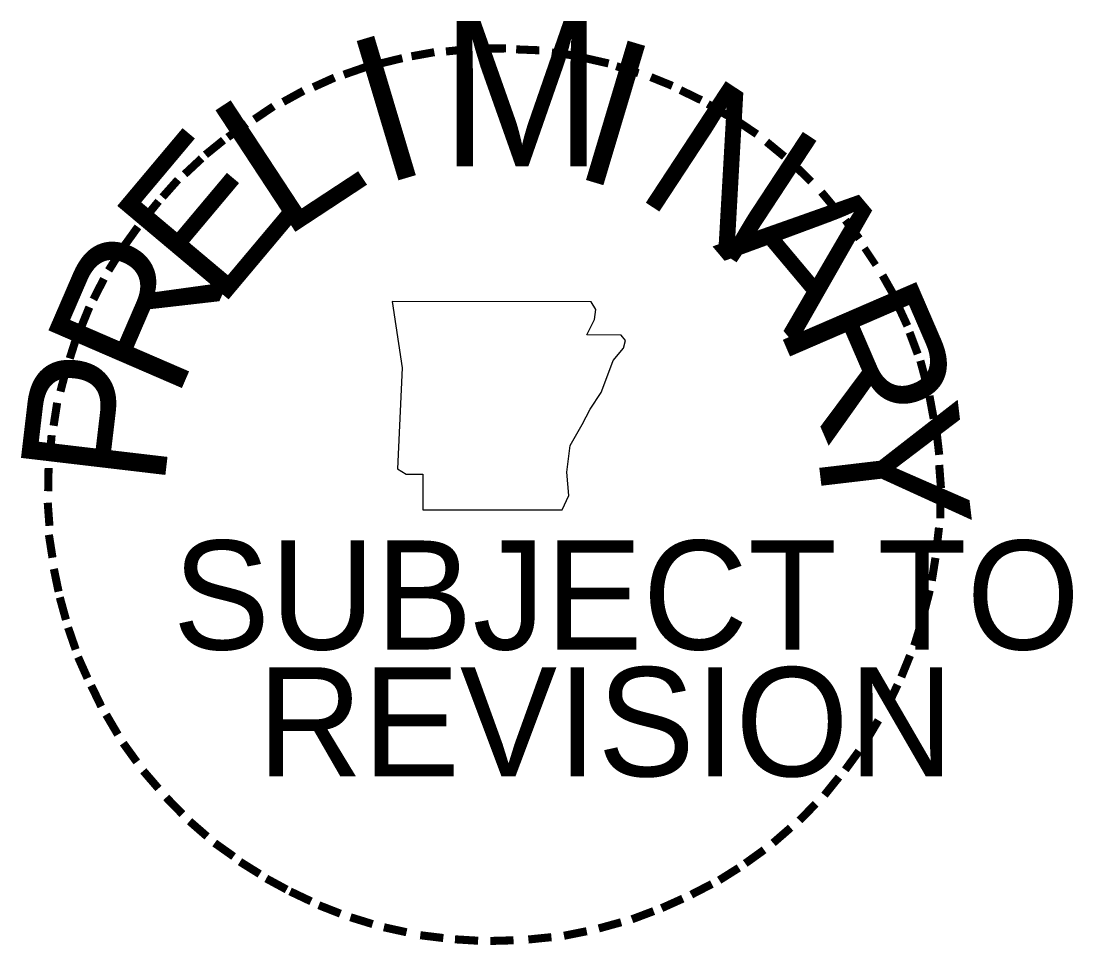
# Model space of a CAD drawing. Extents: x 541267 to 698737, y 790528 to 880942.
# Drawn here: x 687392 to 698737, y 793611 to 803574 of the extents above; entities that cross this region are included whole.
import ezdxf

# ---------------------------------------------------------------- set-up
doc = ezdxf.new("R2010")
doc.units = 0
doc.layers.add('R_Prelim_Stamp', color=7, linetype='Continuous')

msp = doc.modelspace()

# ---------------------------------------------------------------- linework, layer by layer
at = {"layer": 'R_Prelim_Stamp'}
msp.add_lwpolyline([(691394, 800549), (691501, 799833), (691452, 798747), (691547, 798687), (691726, 798687), (691726, 798305), (693229, 798304), (693301, 798459), (693277, 798709), (693313, 798996), (693445, 799223), (693529, 799389), (693648, 799568), (693720, 799759), (693780, 799914), (693888, 800046), (693912, 800129), (693864, 800188), (693494, 800189), (693577, 800356), (693590, 800464), (693540, 800546)], close=True, dxfattribs=at)

# ---------------------------------------------------------------- texts
for s, height, p in [('M', 1568, (691919, 802007)), ('SUBJECT TO', 1175.7, (689029, 796797)), ('REVISION', 1175.7, (689941, 795430))]:
    msp.add_text(s, height=height, dxfattribs=at).set_placement(p)
for s, height, rotation, p in [('I', 1568, 16.6559, (691277, 801801)), ('-', 766, 5.8968, (691960, 802947)), ('-', 766, 0.1862, (692329, 802982)), ('-', 766, 357.743, (692675, 802975)), ('I', 1568, 343.3441, (693300, 801916)), ('-', 766, 13.6302, (691287, 802817)), ('-', 766, 10.2193, (691611, 802895)), ('-', 766, 352.1617, (693031, 802949)), ('-', 766, 347.2049, (693375, 802894)), ('-', 766, 19.1761, (690928, 802702)), ('-', 766, 342.3362, (693679, 802820)), ('-', 766, 24.3072, (690625, 802573)), ('-', 766, 337.8551, (694031, 802713)), ('-', 766, 28.7918, (690322, 802421)), ('N', 1568, 326.6882, (693987, 801710)), ('-', 766, 334.1211, (694333, 802584)), ('L', 1568, 33.3118, (690207, 801207)), ('-', 766, 34.0636, (690036, 802244)), ('-', 766, 329.6409, (694610, 802448)), ('-', 766, 325.8627, (694917, 802275)), ('E', 1568, 49.9677, (689520, 800441)), ('-', 766, 36.2317, (689760, 802055)), ('-', 766, 38.9507, (689532, 801874)), ('-', 766, 320.5297, (695209, 802072)), ('-', 766, 42.9622, (689325, 801675)), ('-', 766, 315.5786, (695496, 801838)), ('-', 766, 48.4231, (689110, 801446)), ('-', 766, 309.8797, (695768, 801575)), ('-', 766, 50.6142, (688917, 801214)), ('A', 1568, 310.0323, (694847, 801147)), ('-', 766, 54.2325, (688720, 800942)), ('-', 766, 306.6522, (696019, 801287)), ('R', 1568, 66.6235, (689059, 799459)), ('-', 766, 58.0706, (688564, 800690)), ('-', 670, 303.6753, (696252, 801015)), ('-', 766, 62.8713, (688415, 800397)), ('-', 766, 299.6684, (696404, 800725)), ('R', 1568, 293.3765, (695540, 800295)), ('-', 766, 67.7743, (688291, 800104)), ('-', 766, 294.6628, (696559, 800432)), ('-', 766, 72.3945, (688186, 799803)), ('-', 766, 290.5728, (696682, 800156)), ('P', 1568, 83.2794, (688929, 798509)), ('-', 766, 285.1233, (696794, 799878)), ('-', 766, 75.461, (688092, 799461)), ('-', 766, 81.2013, (688029, 799120)), ('Y', 1568, 276.7206, (695931, 799353)), ('-', 766, 280.5493, (696890, 799523)), ('-', 766, 85.1863, (687992, 798789)), ('-', 766, 276.5962, (696967, 799156)), ('-', 766, 274.3301, (696996, 798810)), ('-', 766, 89.0622, (687980, 798454)), ('-', 766, 269.9407, (697012, 798508)), ('-', 766, 94.1959, (687997, 798107)), ('-', 766, 263.5172, (697003, 798189)), ('-', 766, 98.9479, (688031, 797788)), ('-', 766, 260.9953, (696969, 797877)), ('-', 766, 101.7149, (688096, 797437)), ('-', 766, 255.7626, (696917, 797552)), ('-', 766, 105.4578, (688174, 797153)), ('-', 766, 252.8681, (696830, 797208)), ('-', 766, 109.0874, (688276, 796851)), ('-', 766, 114.0643, (688398, 796566)), ('-', 766, 247.8887, (696723, 796886)), ('-', 766, 115.7289, (688544, 796270)), ('-', 766, 244.6197, (696598, 796585)), ('-', 766, 120.4471, (688715, 795990)), ('-', 766, 239.0712, (696409, 796225)), ('-', 766, 125.8934, (688907, 795721)), ('-', 766, 233.8452, (696217, 795913)), ('-', 766, 130.7181, (689128, 795457)), ('-', 766, 231.2538, (696011, 795642)), ('-', 766, 134.2238, (689376, 795196)), ('-', 766, 225.7653, (695782, 795372)), ('-', 766, 138.9338, (689627, 794974)), ('-', 766, 221.0851, (695532, 795128)), ('-', 766, 144.6463, (689893, 794780)), ('-', 766, 215.7363, (695270, 794903)), ('-', 766, 148.0898, (690161, 794603)), ('-', 766, 212.2491, (695014, 794717)), ('-', 766, 151.5704, (690438, 794447)), ('-', 766, 207.3568, (694747, 794552)), ('-', 766, 154.6002, (690688, 794329)), ('-', 766, 204.2516, (694449, 794399)), ('-', 766, 158.5612, (690987, 794207)), ('-', 766, 200.7184, (694153, 794269)), ('-', 766, 162.7983, (691315, 794105)), ('-', 766, 195.4743, (693829, 794153)), ('-', 766, 167.5555, (691658, 794027)), ('-', 766, 191.2858, (693480, 794058)), ('-', 766, 173.1155, (692027, 793974)), ('-', 766, 176.5183, (692385, 793949)), ('-', 766, 181.5918, (692741, 793958)), ('-', 766, 185.8167, (693128, 793994))]:
    msp.add_text(s, height=height, rotation=rotation, dxfattribs=at).set_placement(p)

doc.saveas('drawing.dxf')
